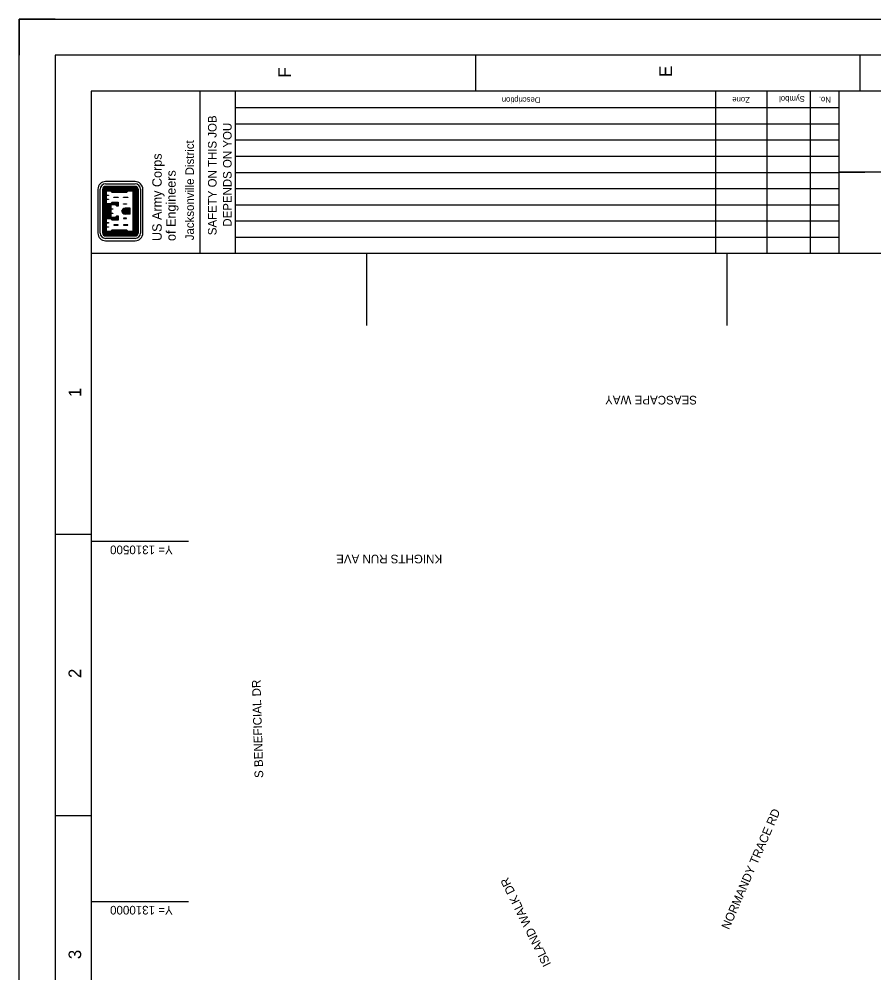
# Model space of a CAD drawing. Extents: x 510517 to 513917, y 1306825 to 1311225.
# Drawn here: x 510517 to 511704, y 1309901 to 1311225 of the extents above; entities that cross this region are included whole.
import ezdxf

# ---------------------------------------------------------------- set-up
doc = ezdxf.new("R2010")
doc.units = 0
for name, color, linetype in [('G-ANNO-NPLT', 7, 'Continuous'), ('G-ANNO-TEXT-LOGO', 7, 'Continuous'), ('G-ANNO-TEXT-TTLB', 7, 'Continuous'), ('G-ANNO-TTLB', 7, 'Continuous'), ('V-ROAD-IDEN', 7, 'Continuous'), ('V-TOPO-COOR-STAT', 7, 'Continuous')]:
    doc.layers.add(name, color=color, linetype=linetype)

msp = doc.modelspace()

# ---------------------------------------------------------------- linework, layer by layer
at = {"layer": 'G-ANNO-NPLT'}
msp.add_lwpolyline([(510517.1, 1306825.1), (510517.1, 1311225.1), (513917.1, 1311225.1), (513917.1, 1306825.1)], close=True, dxfattribs=at)
msp.add_lwpolyline([(510567.1, 1311225.1), (510517.1, 1311225.1), (510517.1, 1311175.1)], dxfattribs=at)
at = {"layer": 'G-ANNO-TEXT-LOGO'}
for p, q in [((510678.2, 1310999.7), (510637.2, 1310999.7)), ((510637.2, 1310996.4), (510678.2, 1310996.4)), ((510637.2, 1310993), (510678.2, 1310993)), ((510626.5, 1310989), (510626.5, 1310928.2)), ((510629.7, 1310928.2), (510629.7, 1310989)), ((510633.1, 1310989), (510633.1, 1310928.2)), ((510634, 1310989), (510634, 1310928.2)), ((510634.9, 1310989), (510634.9, 1310928.2)), ((510635.7, 1310989), (510635.7, 1310928.2)), ((510636.6, 1310989), (510636.6, 1310928.2)), ((510637.2, 1310992.1), (510678.2, 1310992.1)), ((510637.2, 1310991.2), (510678.2, 1310991.2)), ((510637.2, 1310990.4), (510678.2, 1310990.4)), ((510637.2, 1310989.5), (510678.2, 1310989.5)), ((510637.2, 1310988.6), (510677.9, 1310988.6)), ((510637.2, 1310987.8), (510677, 1310987.8)), ((510646, 1310987.1), (510666.8, 1310987.1)), ((510646.8, 1310986.2), (510665.9, 1310986.2)), ((510677, 1310987.8), (510677, 1310929.4)), ((510677.9, 1310988.6), (510677.9, 1310928.6)), ((510678.8, 1310989), (510678.8, 1310928.2)), ((510679.6, 1310989), (510679.6, 1310928.2)), ((510680.5, 1310989), (510680.5, 1310928.2)), ((510681.4, 1310989), (510681.4, 1310928.2)), ((510682.2, 1310989), (510682.2, 1310928.2)), ((510685.7, 1310989), (510685.7, 1310928.2)), ((510689, 1310928.2), (510689, 1310989)), ((510637.4, 1310949.3), (510637.4, 1310967.9)), ((510638.3, 1310949.3), (510638.3, 1310967.9)), ((510639.1, 1310949.3), (510639.1, 1310967.9)), ((510640, 1310949.3), (510640, 1310967.9)), ((510640.9, 1310949.3), (510640.9, 1310967.9)), ((510641.7, 1310949.3), (510641.7, 1310967.9)), ((510642.6, 1310949.3), (510642.6, 1310967.9)), ((510671.1, 1310962.6), (510664.4, 1310962.6)), ((510671.1, 1310961.8), (510664.4, 1310961.8)), ((510671.1, 1310960.9), (510664.4, 1310960.9)), ((510671.1, 1310960), (510664.4, 1310960)), ((510671.1, 1310959.2), (510664.4, 1310959.2)), ((510671.1, 1310958), (510664.4, 1310958)), ((510671.1, 1310957.2), (510664.4, 1310957.2)), ((510671.1, 1310956.3), (510664.4, 1310956.3)), ((510671.1, 1310955.4), (510664.4, 1310955.4)), ((510671.1, 1310954.6), (510664.4, 1310954.6)), ((510671.1, 1310954.6), (510671.1, 1310962.6)), ((510637.2, 1310929.4), (510677, 1310929.4)), ((510637.2, 1310928.6), (510677.9, 1310928.6)), ((510637.2, 1310927.7), (510678.2, 1310927.7)), ((510637.2, 1310926.8), (510678.2, 1310926.8)), ((510645.9, 1310930.1), (510666.9, 1310930.1)), ((510646.8, 1310931), (510665.9, 1310931)), ((510637.2, 1310925.9), (510678.2, 1310925.9)), ((510637.2, 1310925.1), (510678.2, 1310925.1)), ((510637.2, 1310924.2), (510678.2, 1310924.2)), ((510678.2, 1310920.7), (510637.2, 1310920.7)), ((510637.2, 1310917.5), (510678.2, 1310917.5))]:
    msp.add_line(p, q, dxfattribs=at)
for points in [[(510637.2, 1310930.1), (510645.1, 1310930.1), (510646.8, 1310931.8), (510665.9, 1310931.8), (510667.7, 1310930.1), (510676.4, 1310930.1), (510676.4, 1310987.1), (510667.7, 1310987.1), (510665.9, 1310985.3), (510646.8, 1310985.3), (510645.1, 1310987.1), (510637.2, 1310987.1), (510637.2, 1310979.6), (510637.2, 1310973.8), (510637.2, 1310968.4), (510645.1, 1310968.4), (510646.8, 1310970.3), (510653.8, 1310970.3), (510653.8, 1310966.1), (510653.1, 1310966.1), (510651.3, 1310967.9), (510643.5, 1310967.9), (510643.5, 1310960.4), (510643.5, 1310954.6), (510643.5, 1310949.3), (510651.3, 1310949.3), (510653.1, 1310951.1), (510653.8, 1310951.1), (510653.8, 1310946.9), (510646.8, 1310946.9), (510645.1, 1310948.7), (510637.2, 1310948.7), (510637.2, 1310941.2), (510637.2, 1310935.4), (510637.2, 1310930.1)], [(510638.1, 1310930.9), (510644.7, 1310930.9), (510646.5, 1310932.7), (510666.3, 1310932.7), (510668.1, 1310930.9), (510675.5, 1310930.9), (510675.5, 1310986.3), (510668.1, 1310986.3), (510666.3, 1310984.4), (510646.5, 1310984.4), (510644.7, 1310986.3), (510638.1, 1310986.3), (510638.1, 1310980.9), (510641.2, 1310980.9), (510641.2, 1310980.4), (510638.1, 1310980.4), (510638.1, 1310975.1), (510641.2, 1310975.1), (510641.2, 1310974.7), (510638.1, 1310974.7), (510638.1, 1310969.3), (510644.7, 1310969.3), (510646.5, 1310971.1), (510654.6, 1310971.1), (510654.6, 1310965.3), (510652.7, 1310965.3), (510650.9, 1310967.1), (510644.3, 1310967.1), (510644.3, 1310961.7), (510647.4, 1310961.7), (510647.4, 1310961.3), (510644.3, 1310961.3), (510644.3, 1310955.9), (510647.4, 1310955.9), (510647.4, 1310955.4), (510644.3, 1310955.4), (510644.3, 1310950.1), (510650.9, 1310950.1), (510652.7, 1310951.9), (510654.6, 1310951.9), (510654.6, 1310946.1), (510646.5, 1310946.1), (510644.7, 1310947.9), (510638.1, 1310947.9), (510638.1, 1310942.6), (510641.2, 1310942.6), (510641.2, 1310942.1), (510638.1, 1310942.1), (510638.1, 1310936.7), (510641.2, 1310936.7), (510641.2, 1310936.3), (510638.1, 1310936.3), (510638.1, 1310930.9)], [(510646.7, 1310968.9), (510647.2, 1310969.4), (510652.9, 1310969.4), (510652.9, 1310967.6), (510651.6, 1310968.8), (510646.6, 1310968.8)], [(510648.8, 1310978), (510654.6, 1310978), (510654.6, 1310977.5), (510648.8, 1310977.5), (510648.8, 1310978)], [(510662.1, 1310978), (510668, 1310978), (510668, 1310977.5), (510662.1, 1310977.5), (510662.1, 1310978)], [(510662.1, 1310968.9), (510666.2, 1310968.9), (510666.2, 1310968.4), (510662.1, 1310968.4), (510662.1, 1310968.9)], [(510646.7, 1310948.3), (510647.2, 1310947.8), (510652.9, 1310947.8), (510652.9, 1310949.7), (510651.6, 1310948.4), (510646.6, 1310948.4)], [(510648.8, 1310939.1), (510654.6, 1310939.1), (510654.6, 1310939.7), (510648.8, 1310939.7), (510648.8, 1310939.1)], [(510662.1, 1310948.3), (510666.2, 1310948.3), (510666.2, 1310948.8), (510662.1, 1310948.8), (510662.1, 1310948.3)], [(510662.1, 1310939.1), (510668, 1310939.1), (510668, 1310939.7), (510662.1, 1310939.7), (510662.1, 1310939.1)]]:
    msp.add_lwpolyline(points, dxfattribs=at)
for centre, major_axis, start_param, end_param in [((510637.2, 1310988.9), (0, 10.7), 6.283169, 7.853965), ((510637.2, 1310988.9), (0, 7.49), 6.28317, 7.853966), ((510637.2, 1310988.9), (0, 4.02), 6.283169, 7.853965), ((510678.2, 1310988.9), (0, 10.7), 4.712373, 6.28317), ((510678.2, 1310988.9), (0, -7.49), 1.570781, 3.141577), ((510678.2, 1310988.9), (0, 4.02), 4.712373, 6.28317), ((510637.2, 1310988.9), (0, 3.15), 6.283169, 7.853965), ((510637.2, 1310988.9), (0, 2.28), 6.283169, 7.853965), ((510637.2, 1310988.9), (0, 1.41), 6.283169, 7.853965), ((510637.2, 1310988.9), (0, 0.546), 6.283169, 7.853965), ((510678.2, 1310988.9), (0, 3.15), 4.712373, 6.28317), ((510678.2, 1310988.9), (0, 2.28), 4.712373, 6.28317), ((510678.2, 1310988.9), (0, 1.41), 4.712373, 6.28317), ((510678.2, 1310988.9), (0, 0.546), 4.712373, 6.28317), ((510664.8, 1310957), (0, 5.55), 0.068795, 1.29842), ((510664.8, 1310960), (0, -5.55), 4.985832, 6.214359), ((510664.8, 1310957), (0, 4.69), 0.068795, 1.335689), ((510664.8, 1310960), (0, -4.69), 4.947465, 6.21436), ((510664.8, 1310957), (0, 3.82), 0.068795, 1.335689), ((510664.8, 1310960), (0, -3.82), 4.947465, 6.21436), ((510664.8, 1310957), (0, 2.95), 0.068794, 1.335689), ((510664.8, 1310960), (0, -2.95), 4.947465, 6.21436), ((510664.8, 1310960), (0, -2.08), 4.947465, 6.214359), ((510664.8, 1310957), (0, 2.08), 0.068794, 1.335689), ((510637.2, 1310928.2), (0, 10.7), 1.57078, 3.141576), ((510637.2, 1310928.2), (0, 7.49), 1.57078, 3.141576), ((510637.2, 1310928.2), (0, 4.02), 1.57078, 3.141576), ((510637.2, 1310928.2), (0, 3.15), 1.57078, 3.141576), ((510637.2, 1310928.2), (0, 2.28), 1.57078, 3.141576), ((510637.2, 1310928.2), (0, 1.41), 1.57078, 3.141576), ((510637.2, 1310928.2), (0, 0.546), 1.57078, 3.141576), ((510678.2, 1310928.2), (0, -4.02), 6.28317, 7.853966), ((510678.2, 1310928.2), (0, -3.15), 6.28317, 7.853966), ((510678.2, 1310928.2), (0, -2.28), 6.28317, 7.853966), ((510678.2, 1310928.2), (0, -1.41), 6.28317, 7.853966), ((510678.2, 1310928.2), (0, -0.546), 6.28317, 7.853966), ((510678.2, 1310928.2), (0, -10.7), 6.28317, 7.853966), ((510678.2, 1310928.2), (0, -7.49), 6.28317, 7.853966)]:
    msp.add_ellipse(centre, major_axis=major_axis, ratio=0.99964, start_param=start_param, end_param=end_param, dxfattribs=at)
at = {"layer": 'G-ANNO-TTLB'}
for p, q in [((511150.6, 1311175.1), (511150.6, 1311125.1)), ((511683.9, 1311175.1), (511683.9, 1311125.1)), ((510768.3, 1310900.1), (510768.3, 1311125.1)), ((511484.4, 1310900.1), (511484.4, 1311125.1)), ((511555.5, 1310900.1), (511555.5, 1311125.1)), ((511615.5, 1310900.1), (511615.6, 1311125.1)), ((511655.4, 1310900.1), (511655.4, 1311125.1)), ((510817.5, 1310899.5), (510817.5, 1311124.5)), ((510817.5, 1311102.4), (511655.4, 1311102.4)), ((510817.5, 1311079.9), (511655.4, 1311079.9)), ((510817.5, 1311057.4), (511655.4, 1311057.4)), ((510817.5, 1311034.9), (511655.4, 1311034.9)), ((510817.5, 1311012.4), (511655.4, 1311012.4)), ((512514.9, 1311011.9), (511655.4, 1311012.6)), ((511655.4, 1311012.6), (511690.8, 1311012.6)), ((510817.5, 1310989.9), (511655.4, 1310989.9)), ((510817.5, 1310967.4), (511655.4, 1310967.4)), ((510817.5, 1310944.9), (511655.4, 1310944.9)), ((510817.5, 1310922.4), (511655.4, 1310922.4)), ((510617.1, 1310900.1), (513817.1, 1310900.1)), ((510567.1, 1310510.1), (510617.1, 1310510.1)), ((510567.1, 1310120.1), (510617.1, 1310120.1))]:
    msp.add_line(p, q, dxfattribs=at)
for points in [[(513867.1, 1306875.1), (513867.1, 1311175.1), (510567.1, 1311175.1), (510567.1, 1306875.1)], [(510617.1, 1311125.1), (510617.1, 1307000.1), (513817.1, 1307000.1), (513817.1, 1311125.1)]]:
    msp.add_lwpolyline(points, close=True, dxfattribs=at)
at = {"layer": 'V-TOPO-COOR-STAT'}
for p, q in [((511000, 1310800.1), (511000, 1310900.1)), ((511500, 1310800.1), (511500, 1310900.1)), ((510752.1, 1310500), (510617.1, 1310500)), ((510752.1, 1310000), (510617.1, 1310000))]:
    msp.add_line(p, q, dxfattribs=at)

# ---------------------------------------------------------------- texts
at = {"layer": 'G-ANNO-TEXT-TTLB'}
for s, height, rotation, p in [('Description', 8, 180, (511240.6, 1311116.7)), ('Zone', 8, 180, (511531.4, 1311117)), ('Symbol', 8, 180, (511607.7, 1311118.2)), ('No.', 8, 180, (511643.8, 1311117.2)), ('SAFETY ON THIS JOB', 11.9, 90, (510791.2, 1310925.2)), ('DEPENDS ON YOU', 11.9, 90, (510812.1, 1310937)), ('Jacksonville District', 11.9, 90, (510759.8, 1310918.1)), ('US Army Corps', 13.086, 90, (510715.1, 1310917.1)), ('of Engineers', 13.086, 90, (510734.5, 1310917.1))]:
    msp.add_text(s, height=height, rotation=rotation, dxfattribs=at).set_placement(p)
at = {"layer": 'G-ANNO-TTLB'}
for s, p in [('F', (510894.4, 1311143.9)), ('E', (511423.3, 1311144.7)), ('1', (510603.3, 1310700.5)), ('2', (510603.3, 1310310.6)), ('3', (510603.3, 1309920.5))]:
    msp.add_text(s, height=17.5, rotation=90, dxfattribs=at).set_placement(p)
at = {"layer": 'V-ROAD-IDEN'}
for s, rotation, p in [('SEASCAPE WAY', 180, (511458, 1310702.3)), ('KNIGHTS RUN AVE', 180, (511104.3, 1310481.8)), ('S BENEFICIAL DR', 91.6402, (510856.1, 1310172.1)), ('NORMANDY TRACE RD', 66.5995, (511502.5, 1309960.7)), ('ISLAND WALK DR', 116.4892, (511255.9, 1309913.7))]:
    msp.add_text(s, height=12, rotation=rotation, dxfattribs=at).set_placement(p)
at = {"layer": 'V-TOPO-COOR-STAT'}
for s, p in [('Y= 1310500', (510730.4, 1310494.5)), ('Y= 1310000', (510730.4, 1309994.5))]:
    msp.add_text(s, height=12, rotation=180, dxfattribs=at).set_placement(p)

doc.saveas('drawing.dxf')
